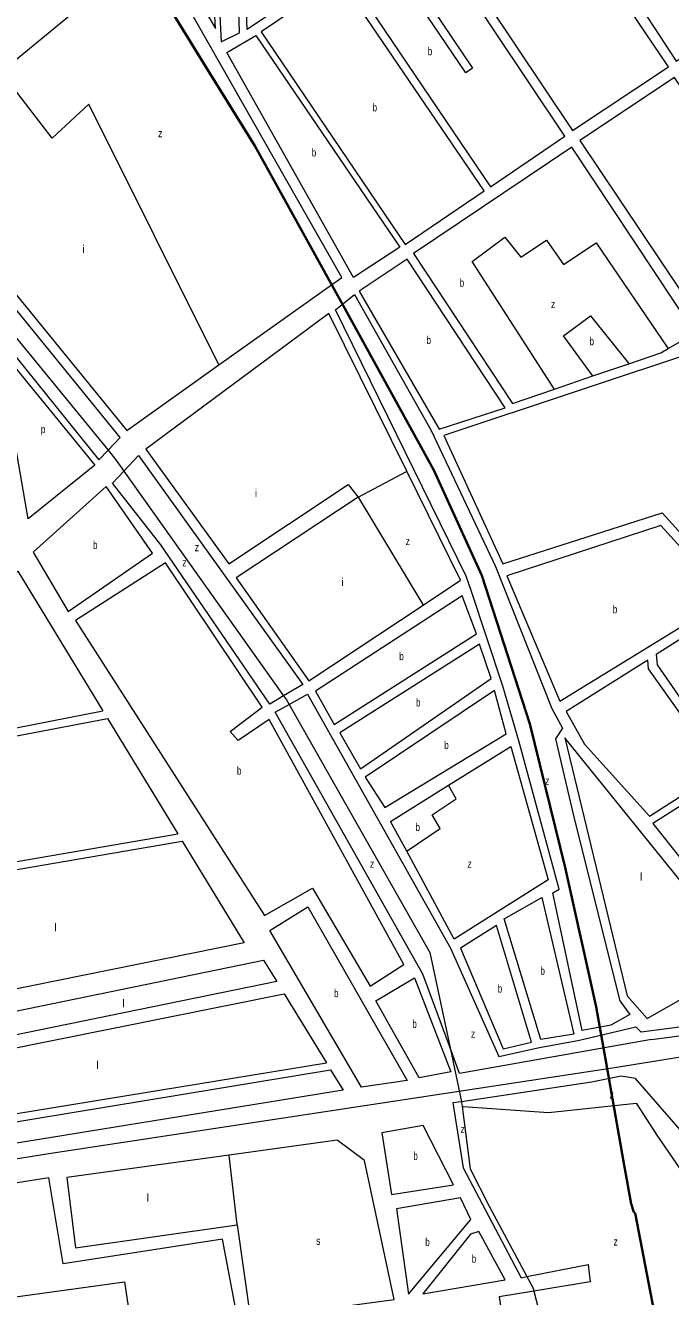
# Model space of a CAD drawing. Extents: x 639657 to 671642, y 222838 to 252123.
# Drawn here: x 657488 to 658293, y 239896 to 241484 of the extents above; entities that cross this region are included whole.
import ezdxf

# ---------------------------------------------------------------- set-up
doc = ezdxf.new("R2010")
doc.units = 0
doc.header["$LTSCALE"] = 4
for name, color, linetype, lineweight in [('1', 7, 'Continuous', 13), ('15', 7, 'Continuous', 13), ('21', 7, 'Continuous', 13), ('57', 7, 'Continuous', 35)]:
    doc.layers.add(name, color=color, linetype=linetype, lineweight=lineweight)
doc.layers.add('7', color=7, linetype='Continuous')

msp = doc.modelspace()

# ---------------------------------------------------------------- linework, layer by layer
at = {"layer": '1'}
for p, q in [((657579.319, 240940.815), (657590.966, 240952.956)), ((657596.621, 240911.77), (657610.757, 240926.892)), ((657372.312, 240586.069), (657584.526, 240627.362)), ((657373.977, 240576.57), (657590.365, 240617.76)), ((657590.365, 240617.76), (657678.023, 240473.609)), ((657400.384, 240425.912), (657678.023, 240473.609)), ((657402.062, 240416.343), (657683.58, 240464.47)), ((658132.92, 240394.14), (658172.647, 240223.625)), ((657440.128, 240199.175), (657810.98, 240273.89)), ((657810.98, 240273.89), (657863.625, 240187.808)), ((657453.886, 240120.68), (657863.625, 240187.808)), ((657356.452, 240094.294), (657868.995, 240179.025))]:
    msp.add_line(p, q, dxfattribs=at)
for points in [[(657860.33, 241640.9), (657901.9, 241570.99), (657764.887, 241478.648), (657755.79, 241724.5), (657781.78, 241742.44), (657783.07, 241676.39), (657837.44, 241679.41), (657848.85, 241660.22), (657848.89, 241574.43), (657859.39, 241574.44)], [(657725.12, 241479.84), (657715.5, 241661.85), (657722.48, 241661.91), (657732.25, 241463.25), (657755.1, 241474.3), (657748.43, 241720.21), (657630.4, 241641.95)], [(658141.77, 241521.44), (658051.17, 241657.51), (657993.36, 241618.38), (658171.07, 241352.58), (658290.74, 241432.02), (658203.12, 241562.34)], [(658416.8, 241516.9), (658329.72, 241647.22), (658215.41, 241569.43), (658300.35, 241439.09)], [(657934.35, 241577.77), (657889.24, 241547.68), (658068.53, 241281.87), (658161.46, 241345.51), (657984.03, 241610.96), (657942.9, 241583.76), (658046.29, 241430.48), (658037.75, 241424.49)], [(658060.51, 241276.97), (657880.39, 241542.4), (657782.11, 241475.49), (657962.23, 241210.06)], [(657897.57, 241168.69), (657739.53, 241449.85), (657775.48, 241471.19), (657955.27, 241206.78)], [(658452.38, 241191.15), (658298.37, 241418.66), (658180.32, 241339.77), (658334.34, 241110.1)], [(658087.02, 241005.93), (657964.53, 241191.82), (657904.7, 241151.56), (658004.5, 240979.45)], [(657574.52, 240934.44), (657491.24, 240867.09), (657453.89, 241081.76)], [(658337.28, 241080.05), (658010.48, 240971.44), (658083.86, 240810.92), (658283.17, 240874.93), (658373.47, 240775.21), (658522.67, 240869.15)], [(657588.73, 240907.68), (657497.51, 240825.76), (657541.16, 240751.42), (657646.43, 240824.33)], [(658281.16, 240858.8), (658088.82, 240795.92), (658155.17, 240639.64), (658364.14, 240767.66)], [(657550.4, 240740.21), (657786.37, 240371.88), (657846.28, 240405.71), (657918.31, 240283.23), (657960.54, 240310.46), (657792.31, 240616.48), (657753.45, 240590.16), (657743.52, 240601.55), (657783.57, 240631.99), (657662.67, 240812.1)], [(658033.42, 240771.14), (657850.06, 240651.9), (657873.54, 240610.17), (658051.03, 240723.45)], [(658054.91, 240710.59), (657880.62, 240600.02), (657906.27, 240555.09), (658069.26, 240667.71)], [(658264.88, 240690.53), (658162.95, 240626.73), (658185.96, 240585.62), (658266.99, 240495.9), (658356.26, 240552.66), (658266.04, 240679.8)], [(658073.69, 240652.7), (657912.28, 240544.39), (657936.8, 240506.43), (658088.14, 240598.54)], [(658387.93, 240313.43), (658161.48, 240593.5), (658239.47, 240271.34), (658264.186, 240243.175)], [(657840.34, 240382.4), (657964.49, 240165.38), (657907.51, 240157.03), (657792.98, 240353.13)], [(658119.621, 240213.571), (658076.24, 240359.26), (658031.32, 240330.94), (658084.457, 240205.193)], [(657973.52, 240293.77), (658018.87, 240176.18), (657979.51, 240168.73), (657925.46, 240265.02)], [(658022.29, 240035.14), (657984.35, 240109.43), (657932.99, 240100.31), (657944.84, 240023.3)], [(657517.06, 240043.8), (657113.18, 239980.21), (657120.7, 239934.36), (657354.17, 239967.04), (657429.04, 239981.26), (657447.95, 239891.45), (657611.68, 239913.87), (657622.24, 239840.98), (657753.5, 239864.1), (657733.93, 239967.47), (657534.98, 239936.3)], [(658044.03, 239991.98), (658030.94, 240019.11), (657951.33, 240005.07), (657966.31, 239898.43)], [(658086.77, 239916.47), (658054.09, 239976.92), (658043.43, 239973.43), (657984.04, 239898.87)]]:
    msp.add_lwpolyline(points, close=True, dxfattribs=at)
for points in [[(657729.344, 241059.466), (657882.961, 241168.707), (657563.691, 241730.618), (657475.29, 241651.12), (657489.45, 241630.27), (657235.73, 241442.18)], [(657590.966, 240952.956), (657606.111, 240968.743), (657225.443, 241436.816), (657196.824, 241434.478)], [(657235.73, 241442.18), (657614.46, 240977.77), (657729.344, 241059.466)], [(657196.824, 241434.478), (657170.743, 241432.347), (657237.722, 241355.266), (657427.498, 241111.734), (657436.429, 241118.437), (657579.319, 240940.815)], [(658324.22, 241099.28), (658170.18, 241331.62), (657972.53, 241198.87), (658096.1, 241011.38), (658148.338, 241029.237), (658196.496, 241045.699), (658241.469, 241061.073)], [(658183.253, 240228.094), (658146.414, 240400.13), (658154.228, 240404.599), (658103.993, 240590.04), (658083.899, 240658.184), (658044.828, 240776.599), (658038.13, 240795.59), (657875.146, 241128.491), (657898.589, 241147.482), (657994.594, 240977.68), (658074.969, 240807.878), (658145.298, 240630.256), (658158.694, 240605.68), (658149.763, 240592.274), (658173.206, 240492.851), (658230.139, 240264.959), (658242.418, 240248.202)], [(657964.045, 240926.672), (657866.93, 241123.93), (657638.32, 240954.32), (657741.7, 240811.15), (657890.83, 240910.22), (657903.33, 240894.2), (657751.02, 240793.5)], [(658241.469, 241061.073), (658281.45, 241074.74), (658290.439, 241079.898), (658324.22, 241099.28)], [(657610.757, 240926.892), (657628.995, 240946.401), (657834.399, 240660.419), (657810.243, 240646.046), (657793.095, 240635.842)], [(657984.529, 240759.521), (658031.1, 240790.47), (657964.045, 240926.672)], [(657793.095, 240635.842), (657656.903, 240834.69), (657596.621, 240911.77)], [(657355.28, 240683.242), (657478.36, 240801.95), (657584.526, 240627.362)], [(657751.02, 240793.5), (657841.89, 240664.73), (657984.529, 240759.521)], [(658343.145, 240740.809), (658275.56, 240697.61), (658276.75, 240684.72), (658370.32, 240549.62), (658271.46, 240486.47), (658401.82, 240322.68), (658558.412, 240420.151)], [(657983.987, 240298.473), (657799.792, 240625.788), (657817.02, 240635.366), (657839.98, 240648.131)], [(657839.98, 240648.131), (658018.593, 240330.869), (658078.875, 240195.697), (658129.668, 240206.868), (658179.903, 240215.805), (658250.232, 240232.562), (658256.93, 240225.859)], [(657964.052, 240451.945), (657943.94, 240489.3), (658016.186, 240534.355), (658094.19, 240583)], [(658094.19, 240583), (658140.79, 240416.24), (658023.16, 240342.16), (657964.052, 240451.945)], [(657683.58, 240464.47), (657760.79, 240337.5), (657427.671, 240270.238)], [(658172.647, 240223.625), (658131.342, 240216.923), (658085.84, 240367.41), (658132.92, 240394.14)], [(657432.386, 240243.339), (657785.24, 240315.98), (657801.71, 240289.05), (657437.407, 240214.696)], [(658772.674, 240310.76), (658461.218, 240252.67), (658256.93, 240225.859)], [(658269.767, 240216.923), (658029.756, 240174.473), (658018.045, 240206.202), (657983.987, 240298.473)], [(658269.767, 240216.923), (658453.403, 240240.941), (658471.264, 240245.409), (658782.4, 240299.07)], [(658242.418, 240248.202), (658218.976, 240234.796), (658183.253, 240228.094)], [(657868.995, 240179.025), (657884.63, 240153.46), (657361.09, 240068.41)], [(658436.99, 239952.88), (658249.68, 240168.08), (658231.62, 240171.08), (658194.93, 240163.52), (658032.32, 240139.078)], [(658032.32, 240139.078), (658021.49, 240137.45), (658034.48, 240056.36), (658107.075, 239919.202), (658114.087, 239920.584)], [(657911.19, 240065.52), (657877.11, 240090.81), (657742.183, 240072.224)], [(657742.183, 240072.224), (657539.61, 240044.32), (657550.57, 239956.34), (657752.35, 239985.18)], [(657752.35, 239985.18), (657768.8, 239867.73), (657948.2, 239892.07), (657911.19, 240065.52)], [(658114.087, 239920.584), (658190.636, 239935.673), (658193.168, 239914.135), (658122.787, 239902.518)], [(658122.787, 239902.518), (658079.24, 239895.33), (658101.74, 239747.59), (658160.247, 239756.96)]]:
    msp.add_lwpolyline(points, dxfattribs=at)
at = {"layer": '15'}
for points in [[(657196.824, 241434.478), (657590.966, 240952.956), (657600.63, 240941.15), (657610.757, 240926.892), (657810.243, 240646.046), (657813.82, 240641.01), (657817.02, 240635.366), (657992.65, 240325.61), (658018.045, 240206.202), (658032.32, 240139.078)], [(658032.32, 240139.078), (658032.451, 240138.08), (658033.082, 240133.261), (658043.34, 240055), (658066.89, 240008.41)], [(658033.082, 240133.261), (658035.083, 240133.122), (658141.23, 240125.73), (658250.35, 240137.42), (658276.46, 240097.44), (658344.57, 239997.66)], [(658066.89, 240008.41), (658114.087, 239920.584), (658121.86, 239906.12), (658122.787, 239902.518)], [(658122.787, 239902.518), (658160.003, 239757.91), (658160.247, 239756.96)]]:
    msp.add_lwpolyline(points, dxfattribs=at)
at = {"layer": '21'}
for points in [[(657729.344, 241059.466), (657567.04, 241385.428), (657521.271, 241342.978), (657457.64, 241425.644), (657544.714, 241497.14), (657489.45, 241630.27)], [(658148.338, 241029.237), (658148.016, 241029.737), (658045.742, 241188.737), (658086.699, 241219.03), (658106.287, 241194.083), (658138.34, 241215.467), (658159.709, 241185.173), (658200.665, 241211.903), (658290.099, 241080.398), (658290.439, 241079.898)], [(658196.496, 241045.699), (658196.131, 241046.199), (658159.709, 241096.075), (658193.542, 241121.022), (658241.069, 241061.573), (658241.469, 241061.073)], [(657903.33, 240894.2), (657963.545, 240926.405), (657964.045, 240926.672)], [(657903.33, 240894.2), (657984.228, 240760.021), (657984.529, 240759.521)], [(657964.052, 240451.945), (657964.552, 240452.288), (658005.757, 240480.563), (657995.71, 240497.32), (658025.851, 240517.428), (658016.471, 240533.855), (658016.186, 240534.355)], [(657752.35, 239985.18), (657752.292, 239985.68), (657742.241, 240071.724), (657742.183, 240072.224)]]:
    msp.add_lwpolyline(points, dxfattribs=at)
at = {"layer": '57'}
for points in [[(657447.288, 241912.324), (657511.934, 241776.214), (657587.108, 241639.406), (657643.183, 241546.51), (657672.194, 241498.195), (657716.29, 241426.571), (657774.351, 241333.081), (657879.884, 241141.945), (657997.947, 240928.104), (658057.811, 240796.62), (658117.568, 240611.18), (658162.022, 240431.636), (658200.564, 240257.588), (658214.124, 240180.626), (658235.678, 240059.886), (658244.186, 240011.534), (658247.755, 240000.928), (658249.128, 240000)], [(658249.128, 240000), (658287.359, 239800.716), (658322.597, 239616.598), (658408.737, 239211.148), (658446.306, 238980.466)]]:
    msp.add_lwpolyline(points, dxfattribs=at)
at = {"layer": '57', "lineweight": 13}
msp.add_lwpolyline([(660000, 240579.681), (659729.838, 240508.731), (659154.006, 240361.508), (658884.968, 240296.195), (658468.447, 240220.857), (658221.071, 240180.865), (657516.999, 240073.954), (657101.087, 240007.445), (657072.54, 240001.797), (657058.514, 240000)], dxfattribs=at)

# ---------------------------------------------------------------- texts
at = {"layer": '7'}
for s, width, p in [('b', 0.75, (657990.252, 241446.415)), ('b', 0.75, (657921.31, 241376.23)), ('z', 0.8, (657653.531, 241343.948)), ('b', 0.75, (657845.439, 241319.94)), ('b', 0.75, (658030.172, 241157.245)), ('z', 0.8, (658144.139, 241130.515)), ('b', 0.75, (657988.713, 241085.635)), ('b', 0.75, (658192.219, 241084.184)), ('p', 0.75, (657507.172, 240974.425)), ('b', 0.75, (657572.273, 240829.55)), ('z', 0.8, (657699.3, 240826.722)), ('z', 0.8, (657962.753, 240834.542)), ('z', 0.8, (657683.671, 240807.731)), ('b', 0.75, (658221.343, 240749.22)), ('b', 0.75, (657954.651, 240690.655)), ('b', 0.75, (657975.574, 240632.84)), ('b', 0.75, (658010.832, 240579.565)), ('b', 0.75, (657751.947, 240547.665)), ('z', 0.8, (658136.901, 240535.154)), ('b', 0.75, (657974.987, 240477.103)), ('z', 0.8, (657918.1, 240431.262)), ('z', 0.8, (658039.78, 240431.262)), ('b', 0.75, (658130.983, 240297.65)), ('b', 0.75, (657873.25, 240269.715)), ('b', 0.75, (658077.644, 240275.335)), ('b', 0.75, (657971.024, 240231.25)), ('z', 0.8, (658044.245, 240219.01)), ('z', 0.8, (658217.276, 240143.046)), ('z', 0.8, (658031.163, 240099.969)), ('b', 0.75, (657972.278, 240066.365)), ('s', 0.8, (657850.92, 239960.266)), ('b', 0.75, (657987.137, 239958.77)), ('z', 0.8, (658222.34, 239959.335)), ('b', 0.75, (658045.156, 239937.895))]:
    msp.add_text(s, height=10, dxfattribs=dict(at, width=width)).set_placement(p)
for s, p in [('i', (657558.823, 241199.304)), ('i', (657774.274, 240894.33)), ('i', (657882.377, 240783.155)), ('l', (658255.207, 240415.08)), ('l', (657523.932, 240351.742)), ('l', (657608.772, 240256.787)), ('l', (657576.399, 240179.706)), ('l', (657639.225, 240014.06))]:
    msp.add_text(s, height=10, dxfattribs=at).set_placement(p)

doc.saveas('drawing.dxf')
